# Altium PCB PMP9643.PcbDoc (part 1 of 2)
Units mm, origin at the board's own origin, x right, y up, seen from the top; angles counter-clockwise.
Board outline 136 x 91.5 mm, 2 copper layers (Top Layer, Bottom Layer), stack 1.575 mm thick; 90 components, 34 nets, 184 pads, 0 vias.
Unrouted connection lines stored in the file: 5.
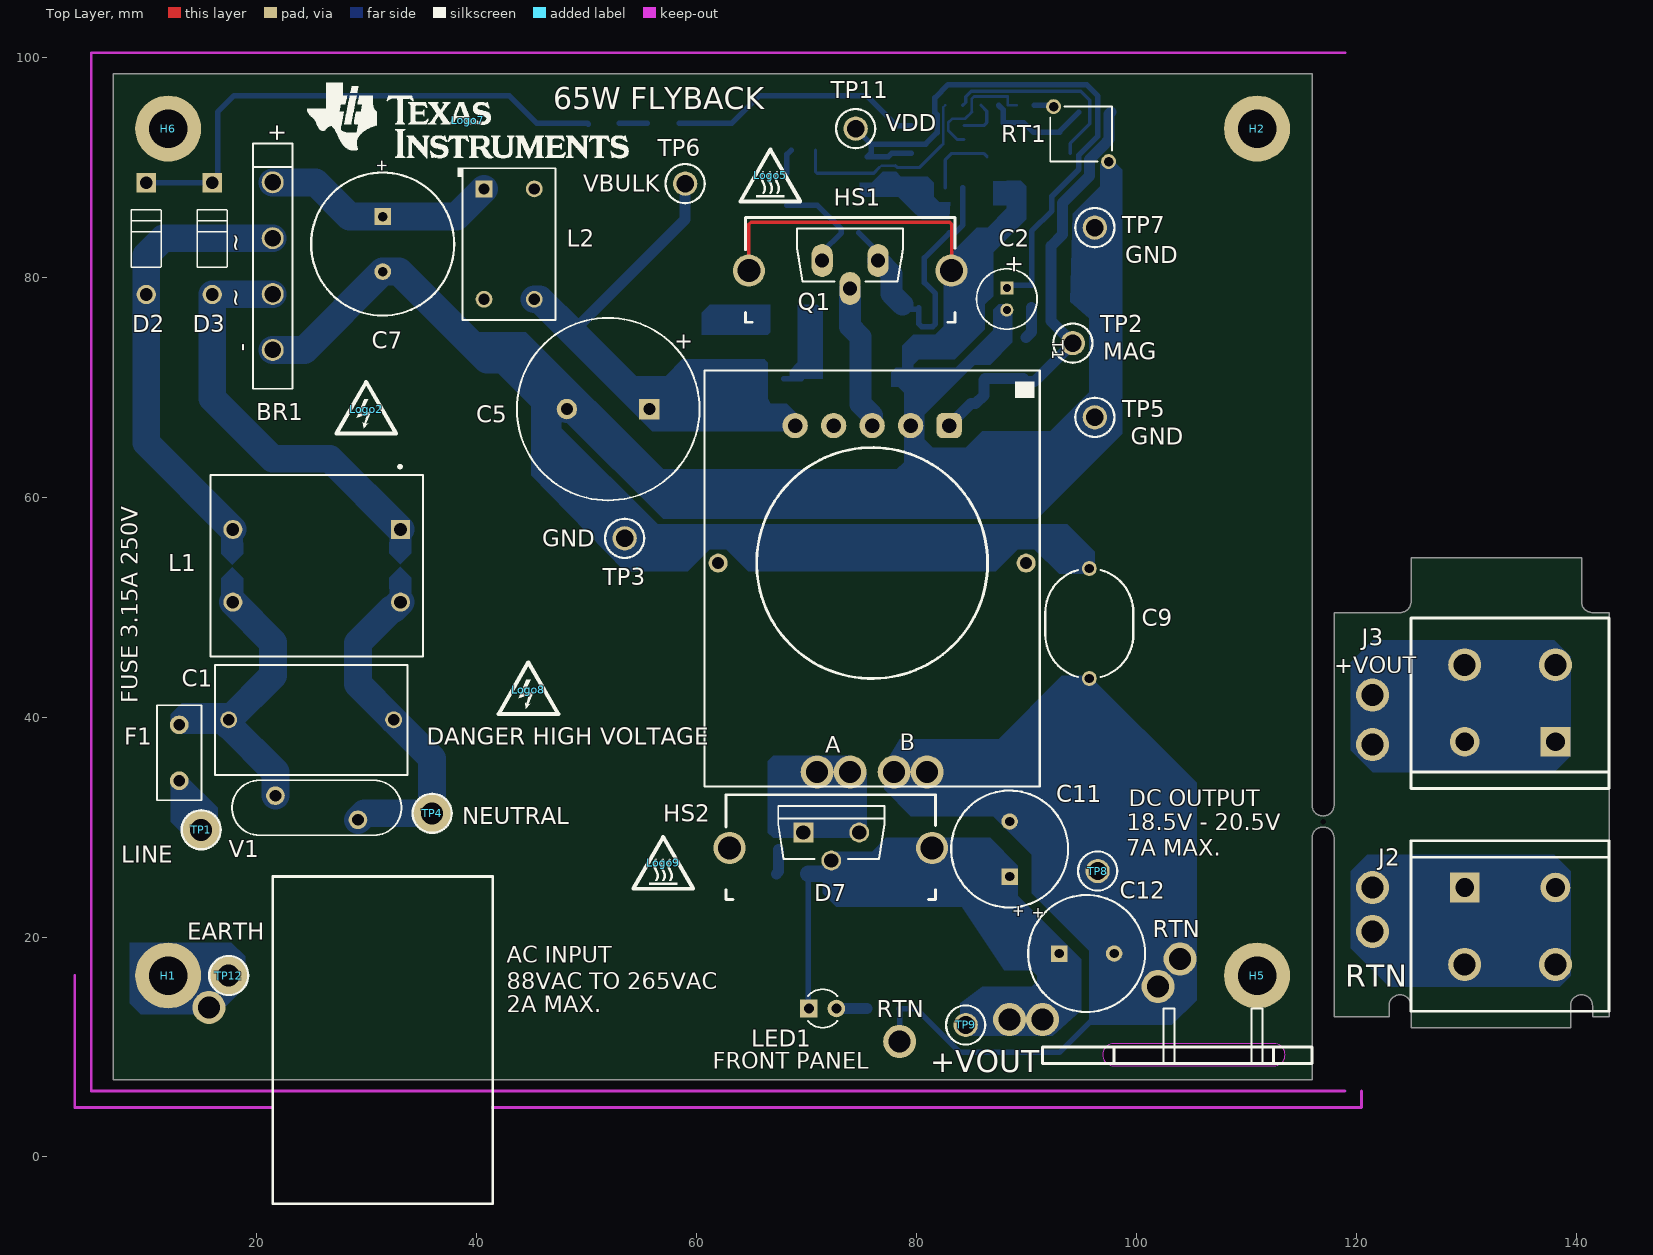
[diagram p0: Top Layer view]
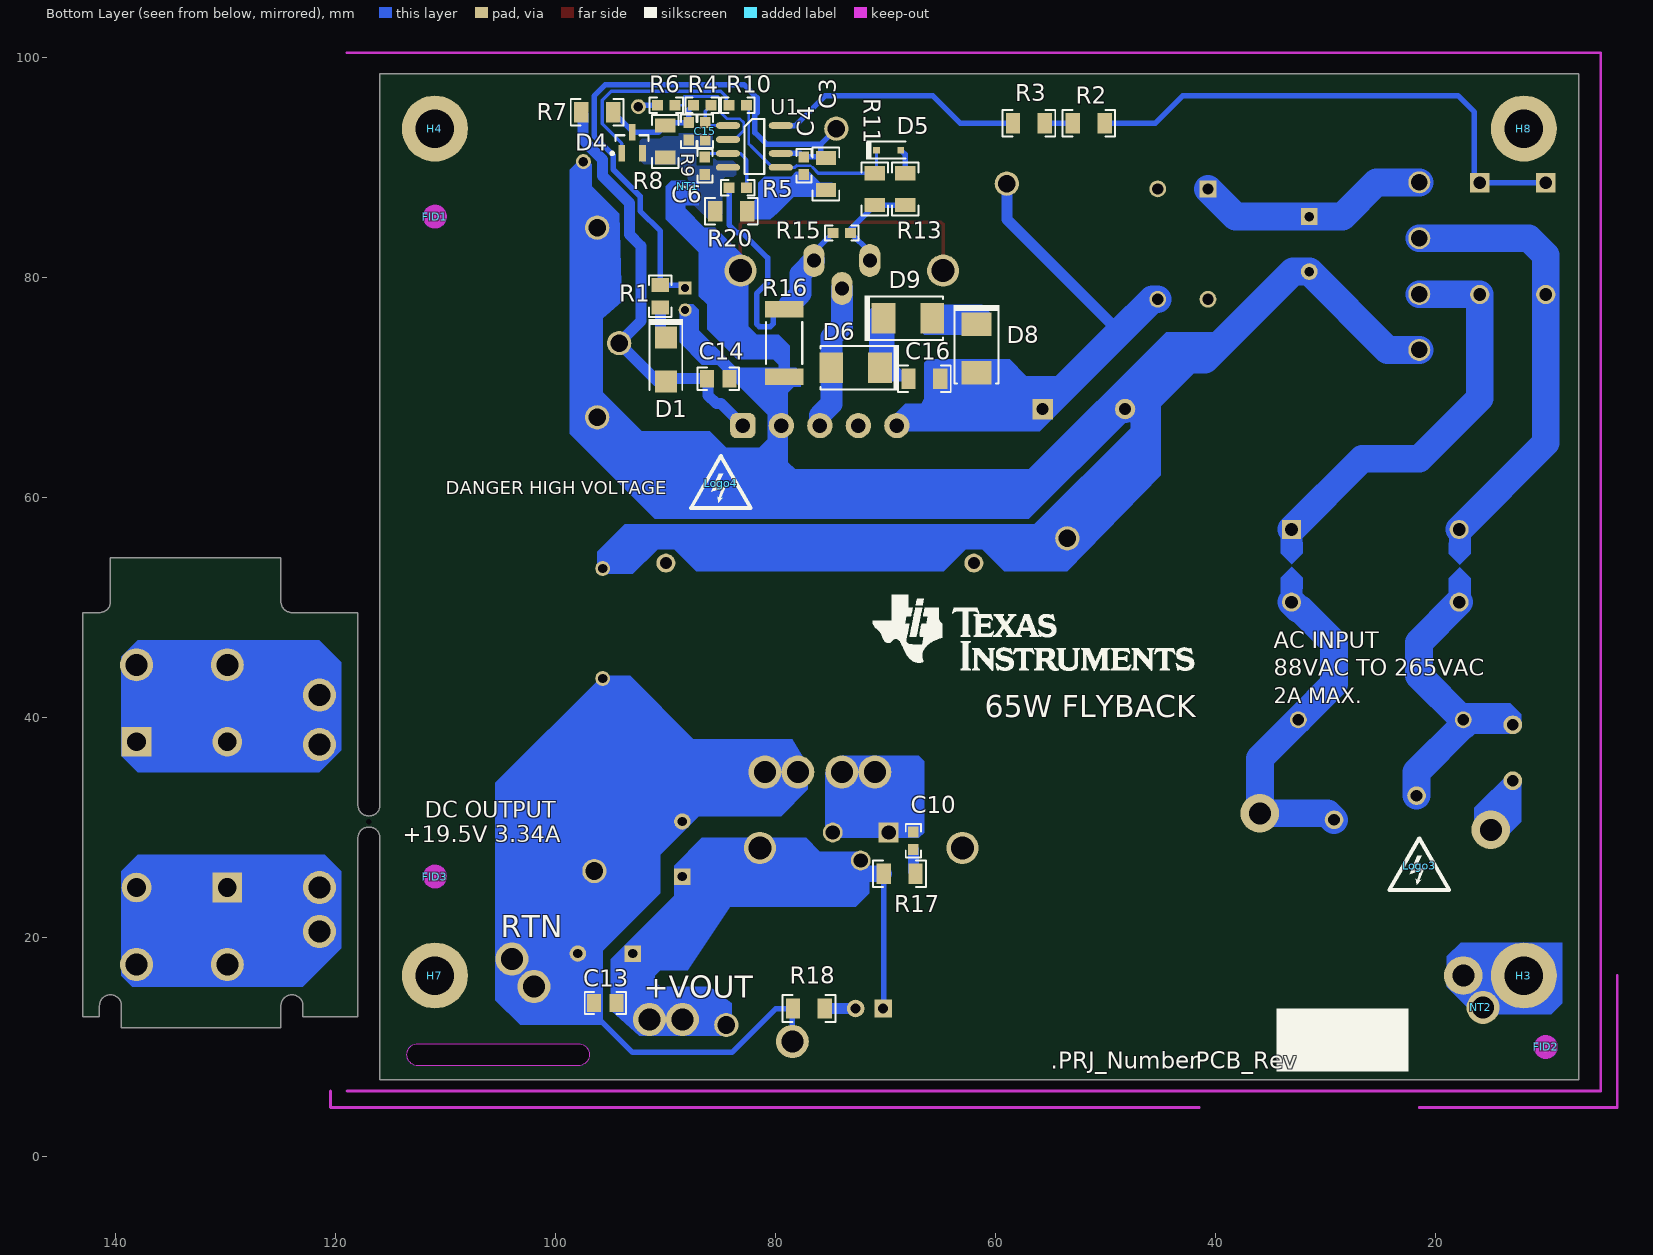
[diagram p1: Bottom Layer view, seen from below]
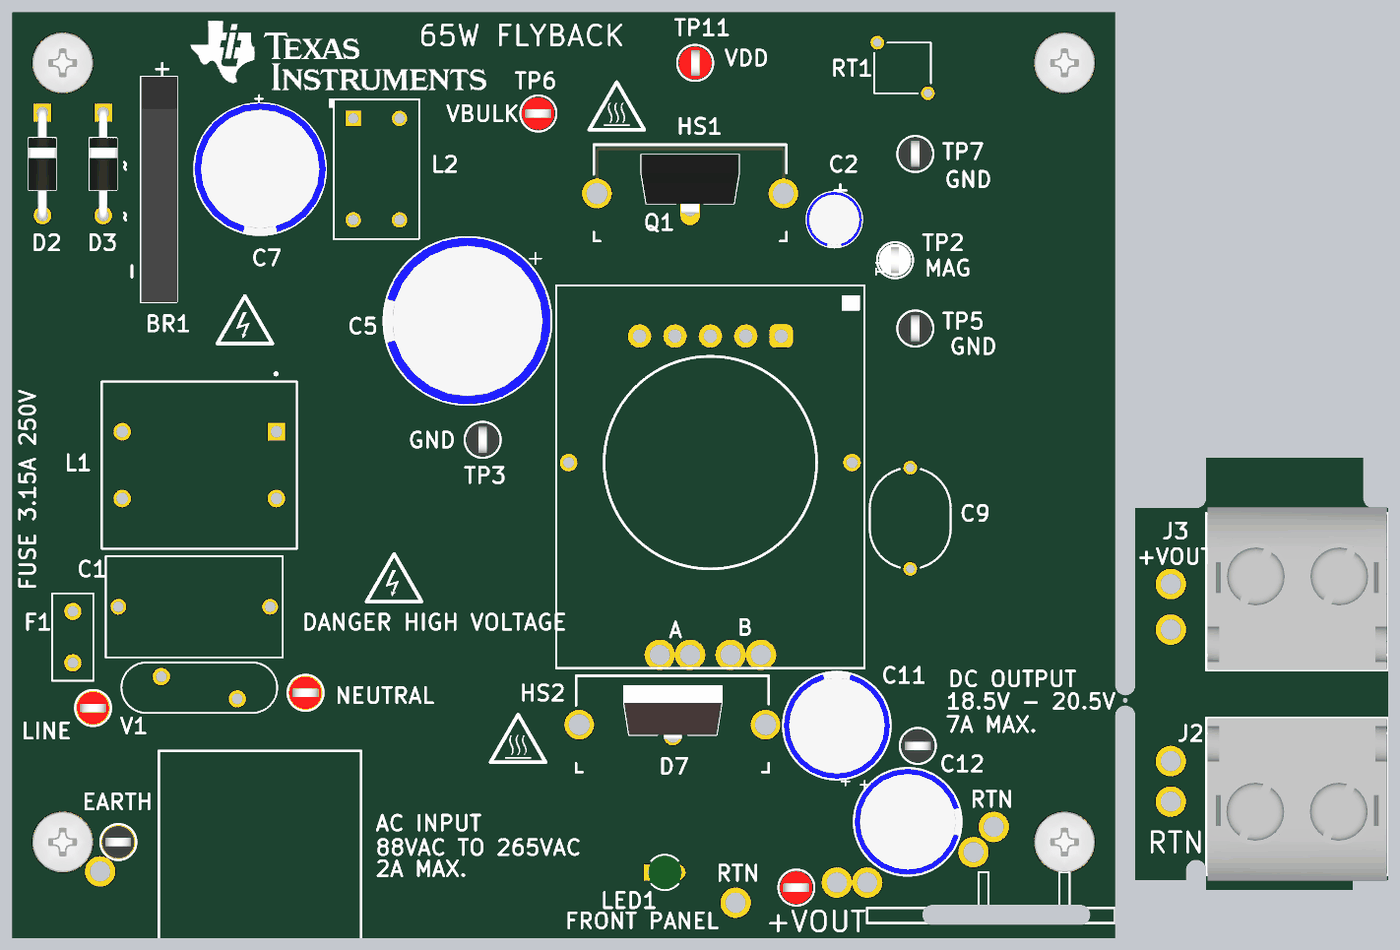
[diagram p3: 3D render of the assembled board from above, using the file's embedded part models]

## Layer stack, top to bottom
Top Layer: signal copper 0.0356
Dielectric: core 1.5037, FR-4, Dk 4.8
Bottom Layer: signal copper 0.0356

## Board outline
7,7 116,7 116,29 cw(c117,29) 117,30 cw(c117,29) 118,29 118,12.75 123,12.75 123,13.75 cw(c124,13.75) 124,14.75 cw(c124,13.75) 125,13.75 125,11.75 139.5,11.75 139.5,13.75 cw(c140.5,13.75) 140.5,14.75 cw(c140.5,13.75) 141.5,13.75 141.5,12.75 143,12.75 143,49.5 141.5,49.5 cw(c141.5,50.5) 140.5,50.5 140.5,54.5 125,54.5 125,50.5 cw(c124,50.5) 124,49.5 118,49.5 118,32 cw(c117,32) 117,31 cw(c117,32) 116,32 116,98.5 7,98.5
cut-out: 96.95,9.3 ccw(c97.95,9.3) 97.95,8.3 112.55,8.3 ccw(c112.55,9.3) 113.55,9.3 ccw(c112.55,9.3) 112.55,10.3 97.95,10.3 ccw(c97.95,9.3)

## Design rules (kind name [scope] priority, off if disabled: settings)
AcuteAngle [All] p1: minimum=4.50000000000000E+0001 checktracksonly=FALSE
AssemblyTestPointUsage [All] p1: valid=2
Clearance "Schematic Clearance Constraint" [InNet('NetR3_1')] p1: gap=1
Clearance Clearance_BoardEdge_MountingHoles [OnCopper and InComponentClass('Mounting Holes') vs IsKeepOut] p2: gap=0.25
Clearance Clearance_BoardEdge_Poly [OnCopper and InPoly vs IsKeepOut] p3: gap=0.5
Clearance Clearance_BoardEdge [OnCopper and Not InComponentClass('Logo') and not InComponentClass('FiducialMark') and not InRegion(1000,500,4000,800) and Not IsKeepout vs IsKeepOut] p4: gap=0.5
Clearance Clearance_Poly [InPolygon] p5: gap=0.3
Clearance [All] p6: gap=0.2
ComponentClearance ComponentClearance_Logo [InComponentClass(Logo)] p1: gap=0.2 collisioncheckmode=3 verticalgap=0.254 showdistances=FALSE
ComponentClearance ComponentClearance_ScrewToNut [(HasFootprint('NY PMS 440 0025 PH')) vs (HasFootprint('Keystone_1902C'))] p2: gap=0.127 collisioncheckmode=3 verticalgap=0.254 showdistances=FALSE
ComponentClearance ComponentClearance_MountingHoles [InComponentClass('Mounting Holes')] p3: gap=0.2 collisioncheckmode=3 verticalgap=0 showdistances=FALSE
ComponentClearance ComponentClearance_SmallPassives [HasFootprint('0201*') or HasFootprint('0402*') or HasFootprint('0508') or HasFootprint('0603*') or HasFootprint('0612') or HasFootprint('0805*') or HasFootprint('0815*') or HasFootprint('0830*') or HasFootprint('1206*') or HasFootprint('1210*') or HasFootprint('1808*') or HasFootprint('1812*') or HasFootprint('1825*') or HasFootprint('2010*') or HasFootprint('2220*') or HasFootprint('2225*') or HasFootprint('2512*') or HasFootprint('2728*') or HasFootprint('3518*') vs HasFootprint('0201*') or HasFootprint('0402*') or HasFootprint('0508') or HasFootprint('0603*') or HasFootprint('0612') or HasFootprint('0805*') or HasFootprint('0815*') or HasFootprint('0830*') or HasFootprint('1206*') or HasFootprint('1210*') or HasFootprint('1808*') or HasFootprint('1812*') or HasFootprint('1825*') or HasFootprint('2010*') or HasFootprint('2220*') or HasFootprint('2225*') or HasFootprint('2512*') or HasFootprint('2728*') or HasFootprint('3518*')] p4: gap=0.508 collisioncheckmode=3 verticalgap=0.254 showdistances=FALSE
ComponentClearance ComponentClearance_THtoSMT [IsThruComponent vs IsSMTComponent] p5: gap=0.2 collisioncheckmode=3 verticalgap=0 showdistances=FALSE
ComponentClearance ComponentClearance_THtoTH [IsThruComponent vs IsThruComponent] p6: gap=0 collisioncheckmode=3 verticalgap=0 showdistances=FALSE
ComponentClearance [All] p7: gap=0.2 collisioncheckmode=3 verticalgap=0.254 showdistances=FALSE
DiffPairsRouting [All] p1: maxlimit=2.54 minlimit=0.254 mostfreqgap=0.254 maxuncoupledlength=25.4
FabricationTestPointUsage TestPointUsage [All] p1: valid=2 allowmultiple=FALSE
FabricationTestpoint Testpoint [All] p1: side=3 testpointundercomponent=TRUE minsize=1.016 maxsize=2.54 preferedsize=1.524 minholesize=0 maxholesize=1.016 preferedholesize=0.813 testpointgrid=0.025 allowsidetop=TRUE allowsidebottom=TRUE usegrid=TRUE gridtolerance=0
FanoutControl Fanout_LCC [IsLCC] p1: bgadir=Out bgaviamode=Centered fanoutstyle=Auto fanoutdirection=Alternating viagrid=0.025 // Fanout_LCC (Default Rule)
FanoutControl Fanout_BGA [IsBGA] p2: bgadir=Out bgaviamode=Centered fanoutstyle=Auto fanoutdirection=Alternating viagrid=0.025 // Fanout_BGA (Default Rule)
FanoutControl Fanout_Default [All] p4: bgadir=Out bgaviamode=Centered fanoutstyle=Auto fanoutdirection=Alternating viagrid=0.025 // Fanout_Default (Default Rule)
FanoutControl Fanout_Small [(CompPinCount < 5)] p5: bgadir=Out bgaviamode=Centered fanoutstyle=Auto fanoutdirection=OutThenIn viagrid=0.025 // Fanout_Small (Default Rule)
Height [All] p1 off: minheight=0 maxheight=25.4 prefheight=12.7
HoleSize [All] p1: absolutevalues=TRUE maxlimit=6.375 minlimit=0.203 maxpercent=80.000 minpercent=20.000
MinimumAnnularRing [All] p1: minimumring=0.2
MinimumSolderMaskSliver MinimumSolderMaskSliver_Logo [InComponentClass('Logo') vs InComponentClass('Logo')] p1: minsoldermaskwidth=0.018
MinimumSolderMaskSliver [All] p2: minsoldermaskwidth=0.102
PlaneConnect [All] p1: planeconnectstyle=Relief reliefexpansion=0.254 reliefentries=4 reliefconductorwidth=0.254 reliefairgap=0.254
PolygonConnect PolygonConnect_25 [All vs IsNamedPolygon('Bottom Layer, Bottom-NEUTRAL')] p1: connectstyle=Relief reliefconductorwidth=0.38 reliefentries=4 polygonreliefangle="90 Angle" airgapwidth=0.254
PolygonConnect PolygonConnect_24 [All vs IsNamedPolygon('Bottom Layer, Bottom-NET00004 1')] p2: connectstyle=Relief reliefconductorwidth=0.38 reliefentries=4 polygonreliefangle="90 Angle" airgapwidth=0.254
PolygonConnect PolygonConnect_23 [All vs IsNamedPolygon('Bottom Layer, Bottom-NET00003')] p3: connectstyle=Relief reliefconductorwidth=0.38 reliefentries=4 polygonreliefangle="90 Angle" airgapwidth=0.254
PolygonConnect PolygonConnect_22 [All vs IsNamedPolygon('Bottom Layer, Bottom-NET00002 2')] p4: connectstyle=Relief reliefconductorwidth=0.38 reliefentries=4 polygonreliefangle="90 Angle" airgapwidth=0.254
PolygonConnect PolygonConnect_21 [All vs IsNamedPolygon('Bottom Layer, Bottom-LINE')] p5: connectstyle=Relief reliefconductorwidth=0.38 reliefentries=4 polygonreliefangle="90 Angle" airgapwidth=0.254
PolygonConnect PolygonConnect_20 [All vs IsNamedPolygon('Bottom Layer, Bottom-GND_EARTH')] p6: connectstyle=Relief reliefconductorwidth=0.38 reliefentries=4 polygonreliefangle="90 Angle" airgapwidth=0.254
PolygonConnect PolygonConnect_19 [All vs IsNamedPolygon('Bottom Layer-No Net')] p7: connectstyle=Direct reliefconductorwidth=0.254 reliefentries=4 polygonreliefangle="90 Angle" airgapwidth=0.254
PolygonConnect PolygonConnect_18 [All vs IsNamedPolygon('Bottom Layer-No Net')] p8: connectstyle=Direct reliefconductorwidth=0.254 reliefentries=4 polygonreliefangle="90 Angle" airgapwidth=0.254
PolygonConnect PolygonConnect_17 [All vs IsNamedPolygon('Bottom Layer-No Net')] p9: connectstyle=Direct reliefconductorwidth=0.254 reliefentries=4 polygonreliefangle="90 Angle" airgapwidth=0.254
PolygonConnect PolygonConnect_16 [All vs IsNamedPolygon('Bottom Layer-No Net')] p10: connectstyle=Direct reliefconductorwidth=0.254 reliefentries=4 polygonreliefangle="90 Angle" airgapwidth=0.254
PolygonConnect PolygonConnect_15 [All vs IsNamedPolygon('Bottom Layer, Bottom-GND 4')] p11: connectstyle=Direct reliefconductorwidth=0.254 reliefentries=4 polygonreliefangle="90 Angle" airgapwidth=0.254
PolygonConnect PolygonConnect_14 [All vs IsNamedPolygon('Bottom Layer, Bottom-GND 4')] p12: connectstyle=Direct reliefconductorwidth=0.254 reliefentries=4 polygonreliefangle="90 Angle" airgapwidth=0.254
PolygonConnect PolygonConnect_13 [All vs IsNamedPolygon('Bottom Layer, Bottom-GND 4')] p13: connectstyle=Relief reliefconductorwidth=0.254 reliefentries=4 polygonreliefangle="90 Angle" airgapwidth=0.254
PolygonConnect PolygonConnect_12 [All vs IsNamedPolygon('Bottom Layer, Bottom-GND 4')] p14: connectstyle=Direct reliefconductorwidth=0.254 reliefentries=4 polygonreliefangle="90 Angle" airgapwidth=0.254
PolygonConnect PolygonConnect_11 [All vs IsNamedPolygon('Bottom Layer, Bottom-GND 4')] p15: connectstyle=Direct reliefconductorwidth=0.254 reliefentries=4 polygonreliefangle="90 Angle" airgapwidth=0.254
PolygonConnect PolygonConnect_10 [All vs IsNamedPolygon('Bottom Layer, Bottom-GND 4')] p16: connectstyle=Direct reliefconductorwidth=0.254 reliefentries=4 polygonreliefangle="90 Angle" airgapwidth=0.254
PolygonConnect PolygonConnect_9 [All vs IsNamedPolygon('Bottom Layer, Bottom-GND 4')] p17: connectstyle=Direct reliefconductorwidth=0.254 reliefentries=4 polygonreliefangle="90 Angle" airgapwidth=0.254
PolygonConnect PolygonConnect_8 [All vs IsNamedPolygon('Bottom Layer, Bottom-GND 4')] p18: connectstyle=Direct reliefconductorwidth=0.254 reliefentries=4 polygonreliefangle="90 Angle" airgapwidth=0.254
PolygonConnect PolygonConnect_7 [All vs IsNamedPolygon('Bottom Layer, Bottom-VOUT 2') Or  IsNamedPolygon('Bottom Layer, Bottom-GND_EARTH') Or  IsNamedPolygon('Bottom Layer, Bottom-NET00004 1') Or  IsNamedPolygon('Bottom Layer, Bottom-VOUT') Or  IsNamedPolygon('Bottom Layer, Bottom-GND 4') Or  IsNamedPolygon('Bottom Layer, Bottom-VIN') Or  IsNamedPolygon('Bottom Layer, Bottom-NET00002 2') Or  IsNamedPolygon('Bottom Layer, Bottom-NET00003') Or  IsNamedPolygon('Bottom Layer, Bottom-VIN 1') Or  IsNamedPolygon('Bottom Layer, Bottom-LINE') Or  IsNamedPolygon('Bottom Layer, Bottom-NET00005') Or  IsNamedPolygon('Bottom Layer, Bottom-GND 2') Or  IsNamedPolygon('Bottom Layer, Bottom-BROWNOUT') Or  IsNamedPolygon('Bottom Layer, Bottom-NEUTRAL') Or  IsNamedPolygon('Bottom Layer, Bottom-NET00009')] p19: connectstyle=Relief reliefconductorwidth=0.2 reliefentries=4 polygonreliefangle="90 Angle" airgapwidth=0.254
PolygonConnect PolygonConnect_6 [All vs IsNamedPolygon('Bottom Layer, Bottom-VOUT 2') Or  IsNamedPolygon('Bottom Layer, Bottom-GND_EARTH') Or  IsNamedPolygon('Bottom Layer, Bottom-NET00004 1') Or  IsNamedPolygon('Bottom Layer, Bottom-VOUT') Or  IsNamedPolygon('Bottom Layer, Bottom-GND 4') Or  IsNamedPolygon('Bottom Layer, Bottom-VIN') Or  IsNamedPolygon('Bottom Layer, Bottom-NET00002 2') Or  IsNamedPolygon('Bottom Layer, Bottom-NET00003') Or  IsNamedPolygon('Bottom Layer, Bottom-VIN 1') Or  IsNamedPolygon('Bottom Layer, Bottom-LINE') Or  IsNamedPolygon('Bottom Layer, Bottom-NET00005') Or  IsNamedPolygon('Bottom Layer, Bottom-GND 2') Or  IsNamedPolygon('Bottom Layer, Bottom-BROWNOUT') Or  IsNamedPolygon('Bottom Layer, Bottom-NEUTRAL') Or  IsNamedPolygon('Bottom Layer, Bottom-NET00009')] p20: connectstyle=Relief reliefconductorwidth=0.35 reliefentries=4 polygonreliefangle="90 Angle" airgapwidth=0.254
PolygonConnect PolygonConnect_5 [All vs IsNamedPolygon('Bottom Layer, Bottom-GND_EARTH')] p21: connectstyle=Relief reliefconductorwidth=0.35 reliefentries=4 polygonreliefangle="90 Angle" airgapwidth=0.254
PolygonConnect PolygonConnect_4 [All vs IsNamedPolygon('Bottom Layer, Bottom-VOUT 2') Or  IsNamedPolygon('Bottom Layer, Bottom-GND_EARTH') Or  IsNamedPolygon('Bottom Layer, Bottom-NET00004 1') Or  IsNamedPolygon('Bottom Layer, Bottom-VOUT') Or  IsNamedPolygon('Bottom Layer, Bottom-GND 4') Or  IsNamedPolygon('Bottom Layer, Bottom-VIN') Or  IsNamedPolygon('Bottom Layer, Bottom-NET00002 2') Or  IsNamedPolygon('Bottom Layer, Bottom-NET00003') Or  IsNamedPolygon('Bottom Layer, Bottom-VIN 1') Or  IsNamedPolygon('Bottom Layer, Bottom-LINE') Or  IsNamedPolygon('Bottom Layer, Bottom-NET00005') Or  IsNamedPolygon('Bottom Layer, Bottom-GND 2') Or  IsNamedPolygon('Bottom Layer, Bottom-BROWNOUT') Or  IsNamedPolygon('Bottom Layer, Bottom-NEUTRAL') Or  IsNamedPolygon('Bottom Layer, Bottom-NET00009')] p22: connectstyle=Relief reliefconductorwidth=0.35 reliefentries=4 polygonreliefangle="90 Angle" airgapwidth=0.254
PolygonConnect PolygonConnect_3 [All vs IsNamedPolygon('Bottom Layer, Bottom-VOUT 2') Or  IsNamedPolygon('Bottom Layer, Bottom-GND_EARTH') Or  IsNamedPolygon('Bottom Layer, Bottom-NET00004 1') Or  IsNamedPolygon('Bottom Layer, Bottom-VOUT') Or  IsNamedPolygon('Bottom Layer, Bottom-GND 4') Or  IsNamedPolygon('Bottom Layer, Bottom-VIN') Or  IsNamedPolygon('Bottom Layer, Bottom-NET00002 2') Or  IsNamedPolygon('Bottom Layer, Bottom-NET00003') Or  IsNamedPolygon('Bottom Layer, Bottom-VIN 1') Or  IsNamedPolygon('Bottom Layer, Bottom-LINE') Or  IsNamedPolygon('Bottom Layer, Bottom-NET00005') Or  IsNamedPolygon('Bottom Layer, Bottom-GND 2') Or  IsNamedPolygon('Bottom Layer, Bottom-BROWNOUT') Or  IsNamedPolygon('Bottom Layer, Bottom-NEUTRAL') Or  IsNamedPolygon('Bottom Layer, Bottom-NET00009')] p23: connectstyle=Relief reliefconductorwidth=0.35 reliefentries=4 polygonreliefangle="90 Angle" airgapwidth=0.254
PolygonConnect PolygonConnect_2 [All vs IsNamedPolygon('Bottom Layer, Bottom-VOUT 2')] p24: connectstyle=Direct reliefconductorwidth=0.254 reliefentries=4 polygonreliefangle="90 Angle" airgapwidth=0.254
PolygonConnect PolygonConnect_1 [All vs IsNamedPolygon('Bottom Layer, Bottom-GND 4')] p25: connectstyle=Direct reliefconductorwidth=0.254 reliefentries=4 polygonreliefangle="90 Angle" airgapwidth=0.254
PolygonConnect [All] p26: connectstyle=Relief reliefconductorwidth=0.254 reliefentries=4 polygonreliefangle="90 Angle" airgapwidth=0.254
RoutingVias [All] p1: holewidth=0.406 width=0.864 viastyle="Through Hole" minholewidth=0.203 minwidth=0.66 maxholewidth=1.016 maxwidth=1.651
SMDToCorner [All] p1: distance=30000
SilkToSilkClearance [All] p1: silktosilkclearance=0
SilkscreenOverComponentPads [All] p1: minsilkscreentomaskgap=0.025
SolderMaskExpansion [All] p1: expansion=0.076
Width [All] p1: maxlimit=2.54 minlimit=0.2 preferedwidth=0.3 checkconnectedcopper=TRUE
13 further rules are at their usual default settings.

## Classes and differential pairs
component class Screw: H1 H2 H5 H6
component class Logo: Logo7
component class PMP9643E1HW: FID1 FID2 FID3 H1 H2 H3 H4 H5 H6 H7 H8 HS1 Logo2 Logo3 Logo4 Logo5 Logo7 Logo8 Logo9 ZZ1 ZZ2 ZZ3 ZZ4
component class FiducialMark: FID1 FID2 FID3
component class AssemblyNote: ZZ1 ZZ2 ZZ3 ZZ4
component class PMP9643E1: BR1 C1 C2 C3 C4 C5 C6 C7 C9 C10 C11 C12 C13 C14 C15 C16 D1 D2 D3 D4 D5 D6 D7 D8 D9 F1 HS2 J1 J2 J3 L1 L2 LED1 NT1 NT2 Q1 R1 R2 R3 R4 R5 R6 R7 R8 R9 R10 R11 R13 R15 R16 R17 R18 R20 RT1 T1 TP1 TP2 TP3 TP4 TP5 TP6 TP7 TP8 TP9 TP11 TP12 U1 V1

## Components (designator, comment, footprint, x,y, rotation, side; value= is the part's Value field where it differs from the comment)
BR1 "GBU4K-E3/45" GBU 21.5,81 r270 top
C1 "BFC233840334" CAPRR1500W80D1750T1000H1650 25,39.75 r180 top
C2 "25ML22MEFC5X5" ML_500x500 88.25,78.01 r270 top
C3 "12063C105KAT2A" 1206 75.45,89.375 r270 bottom
C4 "C0603C104K3RACTU" 0603 77.45,90.125 r270 bottom
C5 "400KXW100MEFC16X30" CAPPR750W80D1600H3000 52,68 r180 top
C6 "06035A121JAT2A" 0603 86.45,90.125 r270 bottom
C7 "UCY2G270MHD1TO" CY_1250x2000 31.5,83 r270 top
C9 "DE1E3KX222MA5BA01" CAPRD1000W60D1000H1400 95.75,48.5 r90 top
C10 "0603YC823KAT2A" 0603 67.5,28.75 r90 bottom
C11 "UHW1V681MPD6" HW_10x20 88.5,28 r90 top
C12 "UHW1V681MPD6" HW_10x20 95.5,18.5 r0 top
C13 "08055C105KAT2A" 0805_HV 95.5,14 r180 bottom
C14 "08051C102KAT2A" 0805_HV 85.25,70.76 r180 bottom
C15 "06035A100JAT2A" 0603 86.425,93.25 r90 bottom
C16 "12062A100JAT2A" 1206 66.5,70.76 r180 bottom
D1 "ES1D-13-F" SMA 90,72.51 r270 bottom
D2 "1N4007" DO-41 10,83.5 r270 top
D3 "1N4007" DO-41 16,83.5 r270 top
D4 "BAV70-V" SOT-23 93.075,92.2 r90 bottom
D5 "BAS316,115" sod-323 69.75,91.55 r180 bottom
D6 "MURS160-13-F" SMB 72.75,71.76 r0 bottom
D7 "MBR20H150CT-E3/45" TO-220AB_100mil 69.75,29.5 r0 top
D8 "1SMB5947BT3G" SMB 61.75,73.51 r270 bottom
D9 "1SMB5949BT3G" SMB 68,76.26 r180 bottom
F1 "39213150000" FUSE_392 13,36.75 r270 top
FID1 "Fiducial" Fiducial10-20 111,85.5 r180 bottom
FID2 "Fiducial" Fiducial10-20 10,10 r180 bottom
FID3 "Fiducial" Fiducial10-20 111,25.5 r180 bottom
H1 "MPMS 003 0005 PH" BuildingFastener_MPMS_003_0005_PH 12,16.5 r90 top locked
H2 "MPMS 003 0005 PH" BuildingFastener_MPMS_003_0005_PH 111,93.5 r0 top locked
H3 "24430" Keystone_24430 12,16.5 r270 bottom locked
H4 "24430" Keystone_24430 111,93.5 r180 bottom locked
H5 "MPMS 003 0005 PH" BuildingFastener_MPMS_003_0005_PH 111,16.5 r0 top locked
H6 "MPMS 003 0005 PH" BuildingFastener_MPMS_003_0005_PH 12,93.5 r0 top locked
H7 "24430" Keystone_24430 111,16.5 r180 bottom locked
H8 "24430" Keystone_24430 12,93.5 r180 bottom locked
HS1 "7173DG" HSINK_7173DG 74,84.988 r0 top
HS2 "7173DG" HSINK_7173DG 72.248,32.5 r0 top
J2 "1546927-2" TE-1546927-2 134,24.5 r0 top
J3 "1546927-2" TE-1546927-2 134,37.75 r180 top
L1 "RLTI-1099" RLTI-1099 25.5,53.75 r270 top
L2 "RLTI-1098" RLTI-1098 43,83 r0 top
LED1 "HLMP1523" LED_HLMP1523 71.5,13.5 r0 top
Logo2 "DANGER HIGH VOLTAGE" IEC_HighVoltage_Small 30,68 r0 top
Logo3 "DANGER HIGH VOLTAGE" IEC_HighVoltage_Small 21.5,26.5 r180 bottom
Logo4 "DANGER HIGH VOLTAGE" IEC_HighVoltage_Small 85,61.25 r180 bottom
Logo5 "CAUTION HOT SURFACE" IEC_HotSurface_Small 66.75,89.25 r0 top
Logo7 "Texas Instruments" TI_Stacked_Overlay_Medium 39.25,94.25 r0 top
Logo8 "DANGER HIGH VOLTAGE" IEC_HighVoltage_Small 44.75,42.5 r0 top
Logo9 "CAUTION HOT SURFACE" IEC_HotSurface_Small 57,26.75 r0 top
NT1 "Net-Tie" Net-Tie_10mil 88,88.25 r0 bottom net-tie
NT2 "Net-Tie" Net-Tie_10mil 15.9,13.6 r0 bottom net-tie
Q1 "STF13NM60ND" TO-220_FullPAK_Offset 74,81.51 r0 top
R1 "ERJ-6RQF4R7V" 0805_HV 90.5,78.26 r270 bottom
R2 "RC1206FR-07100KL" 1206 51.55,94 r180 bottom
R3 "RC1206FR-07100KL" 1206 57,94 r180 bottom
R4 "CRCW0603100RFKEA" 0603 86.7,95.625 r180 bottom
R5 "CRCW06031K00FKEA" 0603 83.45,88.125 r180 bottom
R6 "CRCW06030000Z0EA" 0603 89.95,95.625 r0 bottom
R7 "CRCW120622K6FKEA" 1206 96.25,95 r180 bottom
R8 "CRCW120639K0JNEA" 1206 90.05,92.325 r90 bottom
R9 "ERJ-3EKF4533V" 0603 87.925,93.25 r90 bottom
R10 "RC0603FR-073K9L" 0603 83.45,95.625 r180 bottom
R11 "RC1206FR-0747RL" 1206 71,88 r90 bottom
R13 "CRCW12064R70JNEA" 1206 68.25,88 r90 bottom
R15 "CRCW0603100KFKEA" 0603 74,84.01 r180 bottom
R16 "CSRN2512FKR200" 2512M 79.25,74.01 r90 bottom
R17 "CRCW12061K00FKEA" 1206 68.75,25.75 r180 bottom
R18 "RC1206FR-078K2L" 1206 77,13.5 r180 bottom
R20 "CRCW12060000Z0EA" 1206 84.05,86 r180 bottom
RT1 "B57164K474J" THERM_B57164K 95,93 r180 top
T1 "PartNumber" RM10-5PIN 76,54 r270 top
TP1 "5005" Keystone5005#1 15,29.75 r0 top
TP2 "5007" Keystone5007 94.25,74 r270 top
TP3 "5006" Keystone5006#1 53.5,56.25 r270 top
TP4 "5005" Keystone5005#1 36,31.25 r0 top
TP5 "5006" Keystone5006#1 96.25,67.25 r270 top
TP6 "5005" Keystone5005#2 59,88.5 r0 top
TP7 "5006" Keystone5006#1 96.25,84.5 r270 top
TP8 "5006" Keystone5006#1 96.5,26 r0 top
TP9 "5005" Keystone5005#2 84.5,12 r0 top
TP11 "5005" Keystone5005#2 74.5,93.5 r90 top
TP12 "5006" Keystone5006#2 17.5,16.5 r0 top
U1 "UCC28630D" D0007A_N 81.95,91.875 r180 bottom
V1 "B72214S0271K101" VAR_B72214S0271 25.5,31.75 r0 top
ZZ1 "This Assembly Note is for PCB labels only" AssemblyNoteLabel 78.25,138.25 r0 top
ZZ2 "These assemblies are ESD sensitive, ESD precautions shall be observed." AssemblyNote 78.75,134.25 r0 top
ZZ3 "These assemblies must be clean and free from flux and all contaminants. Use of no clean flux is not acceptable." AssemblyNote 79,127 r0 top
ZZ4 "These assemblies must comply with workmanship standards IPC-A-610 Class 2., unless otherwise specified." AssemblyNote 78.75,130.75 r0 top

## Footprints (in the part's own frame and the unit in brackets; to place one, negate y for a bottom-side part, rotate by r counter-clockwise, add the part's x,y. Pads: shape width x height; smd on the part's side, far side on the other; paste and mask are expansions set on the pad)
0603 [mm] "0603 from SM-752 data"
  rect 1x0.95 smd: 1(-0.8,0) 2(0.8,0)
  silkscreen extent -1.52,-0.69 1.52,0.69, body extent -0.87,-0.47 0.87,0.47, height 0.85
0805_HV [mil] "0805 with 30mil clearance between pads"
  rect 50x63 smd: 1(-40,0) 2(40,0)
  silkscreen extent -74,-40 74,40, body extent -43,-29 43,29, height 43
1206 [mm] "1206 from SM-752 data"
  rect 1.3x1.85 smd: 1(-1.45,0) 2(1.45,0)
  silkscreen extent -2.4,-1.21 2.4,1.21, body extent -1.7,-0.9 1.7,0.9, height 1.35
2512M [mm] "Chip Resistor, Body 6.3x3.2mm, IPC Low Density"
  rect 1.5x3.5 smd: 1(-3.05,0) 2(3.05,0)
  silkscreen extent -1.9,-1.65 1.9,1.65, body extent -3.22,-1.67 3.22,1.67, height 0.71
AssemblyNote [mm] "Assembly Note"
AssemblyNoteLabel [mm] "Assembly Note for PCB Labels"
BuildingFastener_MPMS_003_0005_PH [mil] "MACHINE SCREW PAN PHILLIPS M3"
  round 1 on Mech3: 0(0,0)
  body extent -118,-118 118,118, height 93
CAPPR750W80D1600H3000 [mm] "Capacitor, Electrolytic, Radial; Body 16 x 30 mm (Dia.xH typ); Pin Spacing 7.5 mm (typ)"
  rect 1.85x1.85 hole 1.1: 1(-3.75,0)
  round 1.85 hole 1.1: 2(3.75,0)
  silkscreen extent -8.3,-8.3 8.3,8.3, body extent -8.19,-8.24 8.23,8.24, height 32.01
CAPRD1000W60D1000H1400 [mm] "Disk, Radial Capacitor"
  round 1.35 hole 0.85: 1(-5,0) 2(5,0)
  silkscreen extent -4.86,-4 4.86,4, body extent -5.67,-4 5.7,4, height 13.99
CAPRR1500W80D1750T1000H1650 [mm] "VISHAY/BC COMPONENTS"
  round 1.55 hole 1.05: 1(-7.5,0) 2(7.5,0)
  silkscreen extent -8.75,-5 8.75,5, body extent -8.75,-5 8.75,5, height 16.5
CY_1250x2000 [mm] "Nichicon"
  rect 1.524x1.524 hole 0.85: 1(-2.5,0)
  round 1.524 hole 0.85: 2(2.5,0)
  silkscreen extent -6.5,-6.5 6.5,6.5, body extent -6.47,-6.48 6.47,6.5, height 21.51
D0007A_N [mm] "SOIC, 7-Leads, Body 4.9x3.9mm, Pitch 1.27mm, IPC Medium Density"
  oval 2.2x0.6 smd: 1(-2.4,1.905) 2(-2.4,0.635) 3(-2.4,-0.635) 4(-2.4,-1.905) 5(2.4,-1.905) 6(2.4,-0.635) 8(2.4,1.905)
  silkscreen extent -0.9,-2.5 0.9,2.5, body extent -3,-2.5 3,2.5, height 1.54
DO-41 [mm] "diode"
  rect 1.75x1.75 hole 1.15: 1(-5.08,0)
  round 1.75 hole 1.15: 2(5.08,0)
  silkscreen extent -2.62,-1.37 2.59,1.35, body extent -5.51,-1.36 5.51,1.36, height 2.72
Fiducial10-20 [mm]
  round 1 smd paste-0.5 mask+0.5: 1(0,0)
  Top Layer keep-out circle w1.178: c0,0 r0.5
FUSE_392 [mm] "LITTELFUSE"
  round 1.7 hole 1.05: 1(-2.54,0) 2(2.54,0)
  silkscreen extent -4.32,-2.03 4.32,2.03, body extent -4.25,-2 4.25,2, height 8
GBU [mm] "Comchip / Diodes Inc diode bridge"
  round 2 hole 1.5: 1(-7.62,0) 2(-2.54,0) 3(2.54,0) 4(7.62,0)
  silkscreen extent -11.15,-1.78 11.15,1.78, body extent -11.15,-1.76 11.15,1.8, height 21.55
HSINK_7173DG [mil] "Aavid"
  round 115 hole 82: 1(-362.5,-173.23) 2(362.5,-173.23)
  silkscreen extent -375,-358 375,17, body extent -375,-358 375,12, height 900
HW_10x20 [mm] "Nichicon"
  rect 1.5x1.5 hole 0.85: 1(-2.5,0)
  round 1.5 hole 0.85: 2(2.5,0)
  silkscreen extent -5.31,-5.32 5.31,5.31, body extent -5.21,-5.24 5.24,5.24, height 22.01
IEC_HighVoltage_Small [mm]
  silkscreen extent -2.72,-2.24 2.72,2.47
IEC_HotSurface_Small [mm]
  silkscreen extent -2.72,-2.36 2.72,2.35
Keystone5005#1 [mm] "Keystone Compact loops"
  round 3.5 hole 2: 1(0,0)
  silkscreen extent -1.78,-1.78 1.78,1.78, body extent -1.6,-1.6 1.59,1.59, height 5.72
Keystone5005#2 [mm] "Keystone Compact loops"
  round 2.21 hole 1.6: 1(0,0)
  silkscreen extent -1.78,-1.78 1.78,1.78, body extent -1.6,-1.6 1.59,1.59, height 5.72
Keystone5006#1 [mil] "Keystone Compact loops"
  round 87 hole 63: 1(0,0)
  silkscreen extent -70,-70 70,70, body extent -63,-63 62,63, height 225
Keystone5006#2 [mil] "Keystone Compact loops"
  round 137.8 hole 78.74: 1(0,0)
  silkscreen extent -70,-70 70,70, body extent -63,-63 62,63, height 225
Keystone5007 [mil] "Keystone Compact loops"
  round 87 hole 63: 1(0,0)
  silkscreen extent -70,-70 70,70, body extent -63,-63 62,63, height 225
Keystone_24430 [mm] "Hex Standoff, 5 x 0.5 threaded, Aluminium"
  round 6 hole 3.5: 0(0,0)
  round 0.025 on Mech4: 0(0,0)
  body extent -2.87,-2.5 2.9,2.5, height 5
LED_HLMP1523 [mm] "Everlight Electronics"
  rect 1.6x1.6 hole 0.914: 1(-1.25,0)
  round 1.6 hole 0.914: 2(1.25,0)
  silkscreen extent -1.34,-1.75 1.34,1.75, body extent -1.6,-1.67 1.68,1.67, height 6.2
ML_500x500 [mm] "Rubycon"
  rect 1.2x1.2 hole 0.711: 1(-1,0)
  round 1.2 hole 0.711: 2(1,0)
  silkscreen extent -2.75,-2.75 2.75,2.75, body extent -2.73,-2.75 2.75,2.75, height 6.51
Net-Tie_10mil [mil] "10mil net tie, no solder mask opening, no solder paste"
  rect 10x10 smd paste-5 mask-5: 1(-10,0) 2(10,0)
  Top Layer region: -6,5 6,5 6,-5 -6,-5
RLTI-1098 [mil] "Renco"
  rect 60x60 hole 40 paste+0 mask+1.97: 1(-90,197.5)
  round 60 hole 40 paste+0 mask+1.97: 2(-90,-197.5) 3(90,-197.5) 4(90,197.5)
  silkscreen extent -185,-272 166,275, body extent -166,-272 166,272, height 651
RLTI-1099 [mil] "Renco"
  rect 68x68 hole 45.3 paste+0: 1(-130,300)
  round 68 hole 45.3 paste+0: 2(-130,-300) 3(130,-300) 4(130,300)
  silkscreen extent -360,-380 325,380, body extent -325,-380 325,380, height 650
RM10-5PIN [mm] "Billy"
  rrect50% 2.3x2.3 hole 1.321 paste+0 mask+0.05: 1(-12.5,7)
  round 2.3 hole 1.321 paste+0 mask+0.05: 2(-12.5,3.5) 3(-12.5,0) 4(-12.5,-3.5) 5(-12.5,-7)
  round 3 hole 2 paste+0 mask+0.05: 6(19,-5) 7(19,-2) 8(19,2) 9(19,5)
  round 1.727 hole 1.092 paste+0 mask+0.05: MH1(0,14) MH2(0,-14)
  silkscreen extent -17.5,-15.24 20.32,15.24
SMA [mm] "Molded Diode, 2-Leads, Body 4.3x2.6mm, IPC Medium Density, based on OnSemi component dimensions and land pattern"
  rect 2x2 smd: 1(-2,0) 2(2,0)
  silkscreen extent -3.66,-1.57 2.79,1.57, body extent -2.6,-1.3 2.6,1.3, height 2.42
SMB [mm] "Molded Diode, 2-Leads, Body 5.4x3.6mm, IPC Medium Density, based on OnSemi component dimensions"
  rect 2.159x2.743 smd: 1(-2.21,0) 2(2.21,0)
  silkscreen extent -3.94,-2.08 3.17,2.08, body extent -2.7,-1.8 2.7,1.8, height 2.32
sod-323 [mm] "NXP recommended land pattern"
  rect 0.6x0.6 smd paste-0.05: 1(-1.1,0) 2(1.1,0)
  silkscreen extent -2.06,-0.86 1.53,0.86, body extent -1.3,-0.67 1.3,0.68, height 1.1
SOT-23 [mm] "SOT23, 3-Leads, Body 2.9x1.3mm, Pitch 0.95mm, Lead Span 2.5mm, IPC Medium Density"
  rect 1.5x0.6 smd: 1(-0.95,0.95) 2(-0.95,-0.95) 3(0.95,0)
  silkscreen extent -1.07,-1.5 0.7,1.93, body extent -1.16,-1.45 1.21,1.45, height 1
TE-1546927-2 [mm]
  rect 2.7x2.7 hole 1.7: 1(-4.127,0)
  round 2.7 hole 1.7: 2(4.127,0)
  silkscreen extent -9,-11.25 9,4.25, body extent -8.85,-11.82 8.85,4.24, height 14.99
THERM_B57164K [mm] "EPCOS"
  round 1.35 hole 0.85: 1(-2.5,2.5) 2(2.5,-2.5)
  silkscreen extent -2.8,-2.5 2.8,2.5, body extent -2.8,-2.8 2.8,2.8, height 6.24
TI_Stacked_Overlay_Medium [mm]
  silkscreen extent -14.62,-3.44 14.62,3.42
TO-220_FullPAK_Offset [mm] "Infineon  PG-TO220-3-31"
  oval 1.93x3 hole 1.27: 1(-2.54,0) 2(0,-2.54) 3(2.54,0)
  silkscreen extent -4.82,-1.91 4.83,2.92, body extent -4.82,-2.84 4.83,2.92, height 22.91
TO-220AB_100mil [mm] "High Voltage staggered pins"
  rect 1.8x1.8 hole 1.3: 1(0,0)
  round 1.8 hole 1.3: 2(2.54,-2.54) 3(5.08,0)
  silkscreen extent -2.29,-2.41 7.36,2.43, body extent -2.28,-2.84 7.37,2.43, height 22.88
VAR_B72214S0271 [mm] "EPCOS"
  round 1.7 hole 1.067: 1(-3.75,1.1) 2(3.75,-1.1)
  silkscreen extent -7.7,-2.5 7.7,2.5, body extent -7.74,-2.5 7.7,2.5, height 18.48

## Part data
BR1: "Diode, Switching-Bridge, 800V, 4A, TH"
C1: "CAP, Film, 0.33uF, 630V, +/-20%, TH"
C2: "CAP, AL, 22uF, 25V, +/-20%, TH"
C3: "CAP, CERM, 1uF, 25V, +/-10%, X7R, 1206"
C4: "CAP, CERM, 0.1uF, 25V, +/-10%, X7R, 0603"
C5: "CAP, AL, 100uF, 400V, +/-20%, TH"
C6: "CAP, CERM, 120pF, 50V, +/-5%, C0G/NP0, 0603"
C7: "CAP, AL, 27uF, 400V, +/-20%, TH"
C9: "CAP, CERM, 2200pF, 250V, +/-20%, E, Disc 10x8mm"
C10: "CAP, CERM, 0.082uF, 16V, +/-10%, X7R, 0603"
C11 C12: "CAP, AL, 680uF, 35V, +/-20%, 0.019 ohm, TH"
C13: "CAP, CERM, 1uF, 50V, +/-10%, X7R, 0805"
C14: "CAP, CERM, 1000pF, 100V, +/-10%, X7R, 0805"
C15: "CAP, CERM, 10pF, 50V, +/-5%, C0G/NP0, 0603"
C16: "CAP, CERM, 10pF, 200V, +/-5%, C0G/NP0, 1206"
D1: "Diode, Ultrafast, 200V, 1A, SMA"
D2 D3: "Diode, P-N, 1000V, 1A, TH"
D4: "Diode, Switching, 70V, 0.25A, SOT-23"
D5: "Diode, Ultrafast, 100V, 0.25A, SOD-323"
D6: "Diode, Ultrafast, 600V, 1A, SMB"
D7: library part NTST30100CTG
D8: "Diode, Zener, 82V, 550mW, SMB"
D9: "Diode, Zener, 100V, 550mW, SMB"
F1: "Fuse, 3.15A, 250V, TH"
FID1 FID2 FID3: "Fiducial mark.  There is nothing to buy or mount."
H1 H2 H5 H6: "MACHINE SCREW PAN PHILLIPS M3"
H3 H4 H7 H8: library part 1902C, "HEX STANDOFF M3 ALUMINUM 5MM"
HS1 HS2: "BOARD LEVEL HEATSINK .375\" TO-220"
J2 J3: library part TE-1546927-2
L1: "Inductor, Toroid, ?, 4.5mH, A, 0.05 ohm, TH"
L2: "Inductor, Toroid, ?, 47.7uH, A, 0.04 ohm, TH"
LED1: "LED, Green, TH"
Logo2 Logo3 Logo4 Logo8: library part IEC_HighVoltage, "IEC 61010-1 High Voltage Warning"
Logo5 Logo9: library part IEC_HotSurface, "IEC 61010-1 Hot Surface Warning"
Logo7: library part TI_Logo, "Texas Instrument Corporate Signature"
NT1 NT2: "Single point connection between nets."
Q1: "MOSFET, N-CH, 600V, 11A, TO-220 FullPAK"
R1: "RES, 4.70 ohm, 1%, 0.125W, 0805"
R2 R3: "RES, 100k ohm, 1%, 0.25W, 1206"
R4: "RES, 100 ohm, 1%, 0.1W, 0603"
R5: "RES, 1.00k ohm, 1%, 0.1W, 0603"
R6: "RES, 0 ohm, 5%, 0.1W, 0603"
R7: "RES, 22.6k ohm, 1%, 0.25W, 1206"
R8: "RES, 39k ohm, 5%, 0.25W, 1206"
R9: library part RC0603FR-07180KL
R10: "RES, 3.90k ohm, 1%, 0.1W, 0603"
R11: "RES, 47.0 ohm, 1%, 0.25W, 1206"
R13: "RES, 4.7 ohm, 5%, 0.25W, 1206"
R15: "RES, 100k ohm, 1%, 0.1W, 0603"
R16: "RES, 0.2 ohm, 1%, 2W, 2512"
R17: "RES, 1.00k ohm, 1%, 0.25W, 1206"
R18: "RES, 8.20k ohm, 1%, 0.25W, 1206"
R20: "RES, 0 ohm, 5%, 0.25W, 1206"
RT1: "Thermistor NTC, 470k ohm, 5%, Disc, 5.5x5mm"
T1: library part RM10-5pin, "RM10-5pin"
TP1 TP4 TP6 TP9 TP11: "Test Point, Compact, Red, TH"
TP2: "Test Point, Compact, White, TH"
TP3 TP5 TP7 TP8 TP12: "Test Point, Compact, Black, TH"
U1: "Green-Mode Flyback Controller, D0007A"
V1: "Varistor, 430V, 4.5KA, TH"
ZZ1: library part AssemblyNoteLabel
ZZ2 ZZ3 ZZ4: library part AssemblyNote

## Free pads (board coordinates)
  round 0 hole 0.5 unplated: 0(6.5,54) 0(61.5,99) 0(61.5,6.5) 0(117,30.5) 0(132.5,11.25) 0(132.5,55) 0(143.5,30.5)
  round 3 hole 2: 0(15.7,13.6) 0(78.5,10.5) 0(88.5,12.5) 0(91.5,12.5) 0(102,15.5) 0(104,18) 0(121.5,20.5) 0(121.5,24.5) 0(121.5,37.5) 0(121.5,42) 0(129.872,17.5) 0(129.872,44.75) 0(138.127,17.5) 0(138.127,44.75)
